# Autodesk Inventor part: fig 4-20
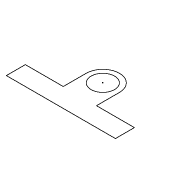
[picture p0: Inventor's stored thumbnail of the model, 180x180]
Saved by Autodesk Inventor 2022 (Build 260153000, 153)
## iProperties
Created: 2004-05
Part Number: fig 4-20
Document SubType Name: Modeling
Designer: CADCIM Technologies
Manufacturer: Standard
Standards Organization: Custom
Density: 1 g/cm^3
Material: Generic
Appearance: Default
Author: CADCIM Technologies
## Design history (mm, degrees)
sketch "Sketch1"
  geometry: L1 (21.396, 25)-(21.396, 15.181); L2 (21.396, 15.181)-(77.829, 15.181); L3 (77.829, 15.181)-(77.829, 25); L4 (77.829, 25)-(58.204, 25); L5 (58.204, 25)-(58.204, 36.886); L6 (41.021, 36.886)-(41.021, 25); L7 (41.021, 25)-(21.396, 25); C1 r 6.072 at (49.612, 36.886); A1 r 8.592 centre (49.612, 36.886) between (58.204, 36.886) and (41.021, 36.886)
  constraints: 14 end point, 5 parallel, 2 centre point, 2 equal length, 2 point on circle, 2 tangent, 1 coincident, 1 perpendicular, 1 vertical, 1 other
